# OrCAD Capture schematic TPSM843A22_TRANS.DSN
size D; title: TPSM843A22 4V to 18V Input, 12A Buck Power Module; rev: 1.0; note: Datasheet: SLUSFA5 EVM: N/A; note: with Internally Compensated Advanced CurrentMode Control
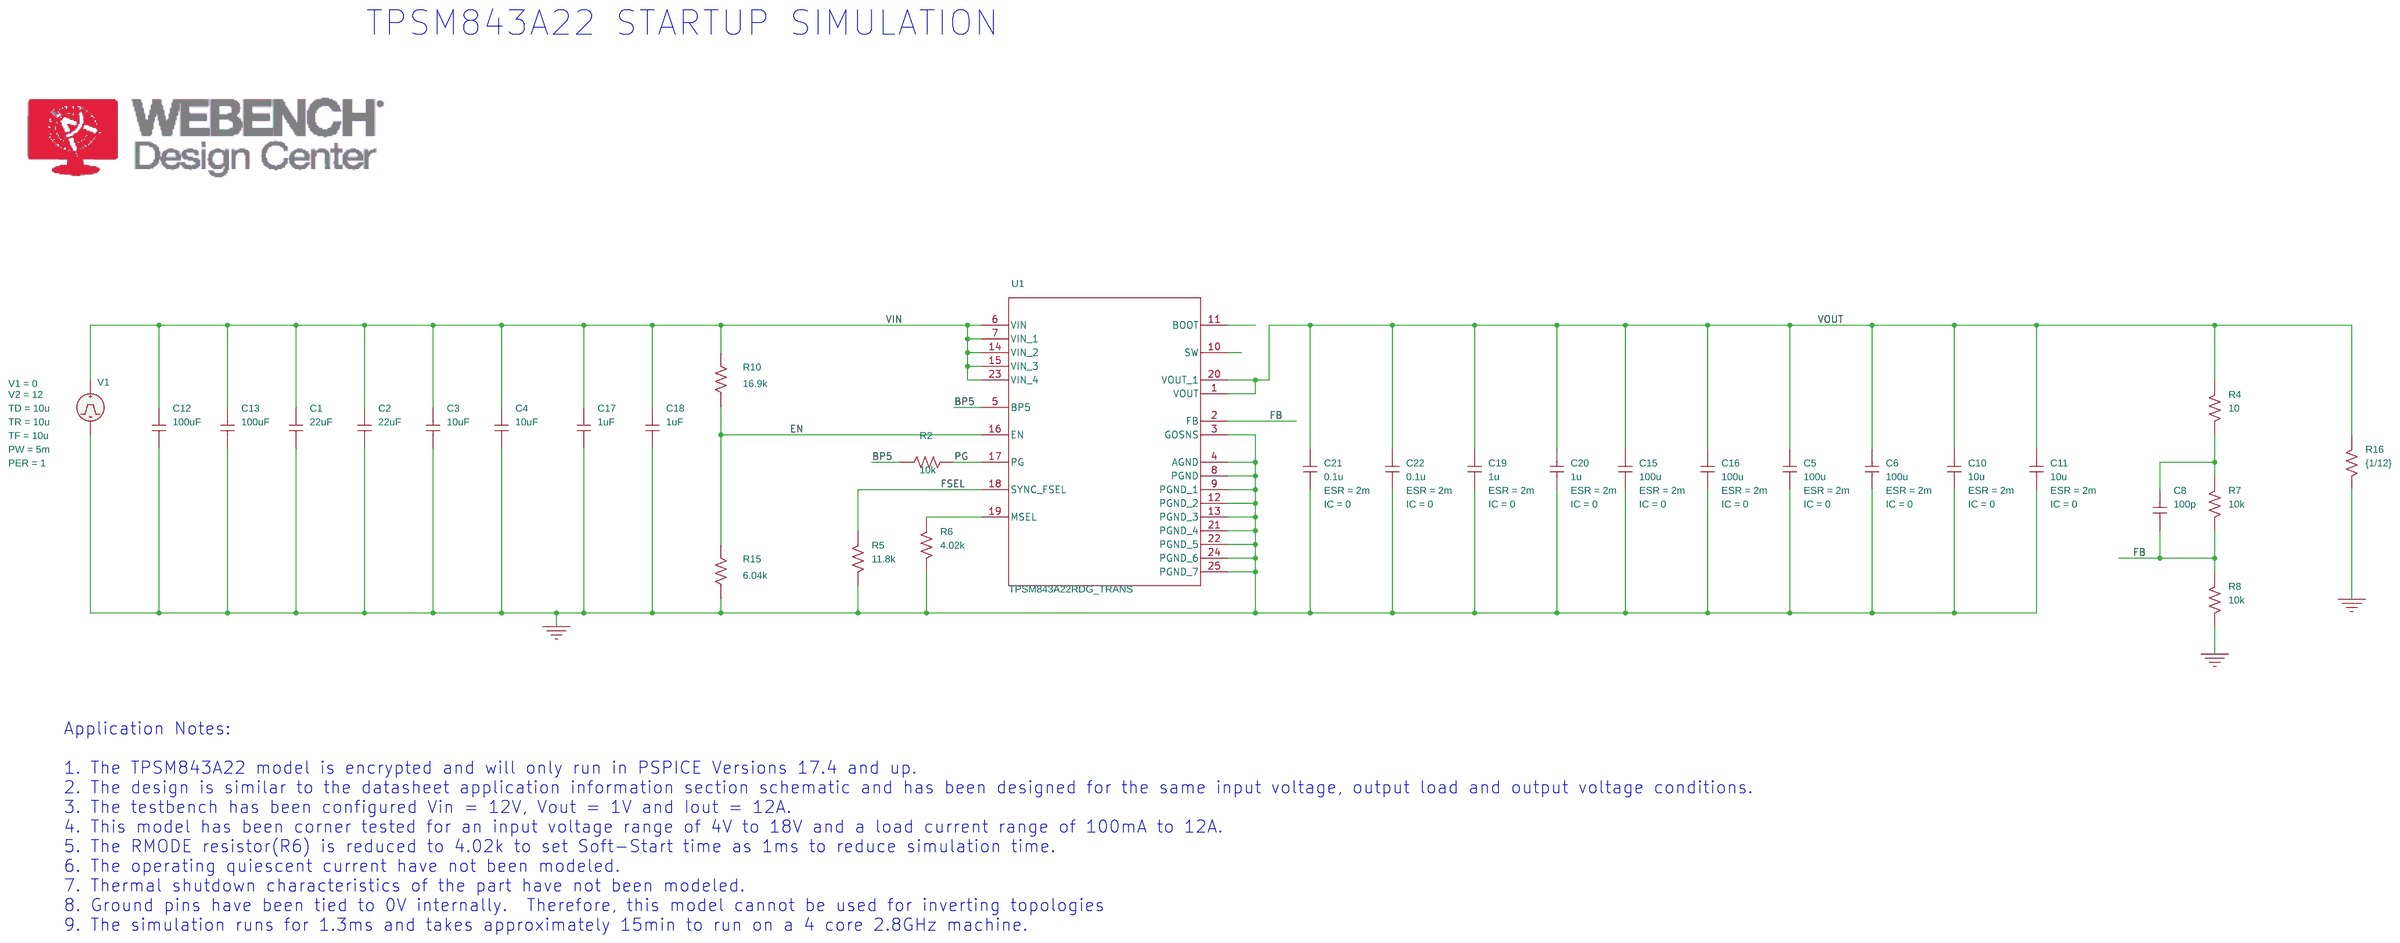
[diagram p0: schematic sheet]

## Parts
C1  22uF  [cap196]
C2  22uF  [cap196]
C3  10uF  [cap196]
C4  10uF  [cap196]
C5  100u  [RAD/CK05]
C6  100u  [RAD/CK05]
C8  100p  [cap196]
C10  10u  [RAD/CK05]
C11  10u  [RAD/CK05]
C12  100uF  [cap196]
C13  100uF  [cap196]
C15  100u  [RAD/CK05]
C16  100u  [RAD/CK05]
C17  1uF  [cap196]
C18  1uF  [cap196]
C19  1u  [RAD/CK05]
C20  1u  [RAD/CK05]
C21  0.1u  [RAD/CK05]
C22  0.1u  [RAD/CK05]
R2  10k  [AXRC05]
R4  10  [AXRC05]
R5  11.8k  [AXRC05]
R6  4.02k  [AXRC05]
R7  10k  [AXRC05]
R8  10k  [AXRC05]
R10  16.9k  [AXRC05]
R15  6.04k  [AXRC05]
R16  {1/12}  [AXRC05]
U1  TPSM843A22RDG_TRANS  [RDG0025A-MFG]
V1  VPULSE

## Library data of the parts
C1-C4 C8 C12 C13 C17 C18 = C
C5 C6 C10 C11 C15 C16 C19-C22 = C: AppProp: InductiveSlave:;SRF:;PrevCap:22u;PrevESL:; ESR: 2m; IC: 0
R2 R4-R8 R10 R15 R16 = R
U1 = TPSM843A26RDG_TRANS: PSpiceTemplate: X^@REFDES  %SYNC_FSEL %BP5 %PGND %FB %VIN_1 %EN %PG %MSEL %SW %BOOT %GOSNS %AGND %PGND_1 %PGND_2 %PGND_3 %VIN %VIN_2 %VIN_3 %VIN_4 %PGND_4 %PGND_5 %PGND_6 %PGND_7 %VOUT %VOUT_1 @MODEL
V1 = VPULSE: PER: 1; PW: 5m; TD: 10u; TF: 10u; TR: 10u; V1: 0; V2: 12

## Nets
VIN: C1.1 C2.1 C3.1 C4.1 C12.1 C13.1 C17.1 C18.1 R10.2 U1.6(VIN) U1.7(VIN_1) U1.14(VIN_2) U1.15(VIN_3) U1.23(VIN_4) V1.1(+)
0: C1.2 C2.2 C3.2 C4.2 C5.2 C6.2 C10.2 C11.2 C12.2 C13.2 C15.2 C16.2 C17.2 C18.2 C19.2 C20.2 C21.2 C22.2 R5.2 R6.2 R8.2 R15.1 R16.2 U1.3(GOSNS) U1.4(AGND) U1.8(PGND) U1.9(PGND_1) U1.12(PGND_2) U1.13(PGND_3) U1.21(PGND_4) U1.22(PGND_5) U1.24(PGND_6) U1.25(PGND_7) V1.2(-)
BP5: R2.1 U1.5(BP5)
EN: R10.1 R15.2 U1.16(EN)
FB: C8.2 R7.2 R8.1 U1.2(FB)
FSEL: R5.1 U1.18(SYNC_FSEL)
PG: R2.2 U1.17(PG)
VOUT: C5.1 C6.1 C10.1 C11.1 C15.1 C16.1 C19.1 C20.1 C21.1 C22.1 R4.1 R16.1 U1.1(VOUT) U1.20(VOUT_1)
N16772420: C8.1 R4.2 R7.1
N16855264: R6.1 U1.19(MSEL)

Not connected (* = marked no-connect by the designer): U1 10(SW) 11(BOOT)

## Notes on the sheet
- TPSM843A22 STARTUP SIMULATION
- Application Notes:
  1. The TPSM843A22 model is encrypted and will only run in PSPICE Versions 17.4 and up.
  2. The design is similar to the datasheet application information section schematic and has been designed for the same input voltage, output load and output voltage conditions.
  3. The testbench has been configured Vin = 12V, Vout = 1V and Iout = 12A.
  4. This model has been corner tested for an input voltage range of 4V to 18V and a load current range of 100mA to 12A.
  5. The RMODE resistor(R6) is reduced to 4.02k to set Soft-Start time as 1ms to reduce simulation time.
  6. The operating quiescent current have not been modeled.
  7. Thermal shutdown characteristics of the part have not been modeled.
  8. Ground pins have been tied to 0V internally.  Therefore, this model cannot be used for inverting topologies
  9. The simulation runs for 1.3ms and takes approximately 15min to run on a 4 core 2.8GHz machine.
